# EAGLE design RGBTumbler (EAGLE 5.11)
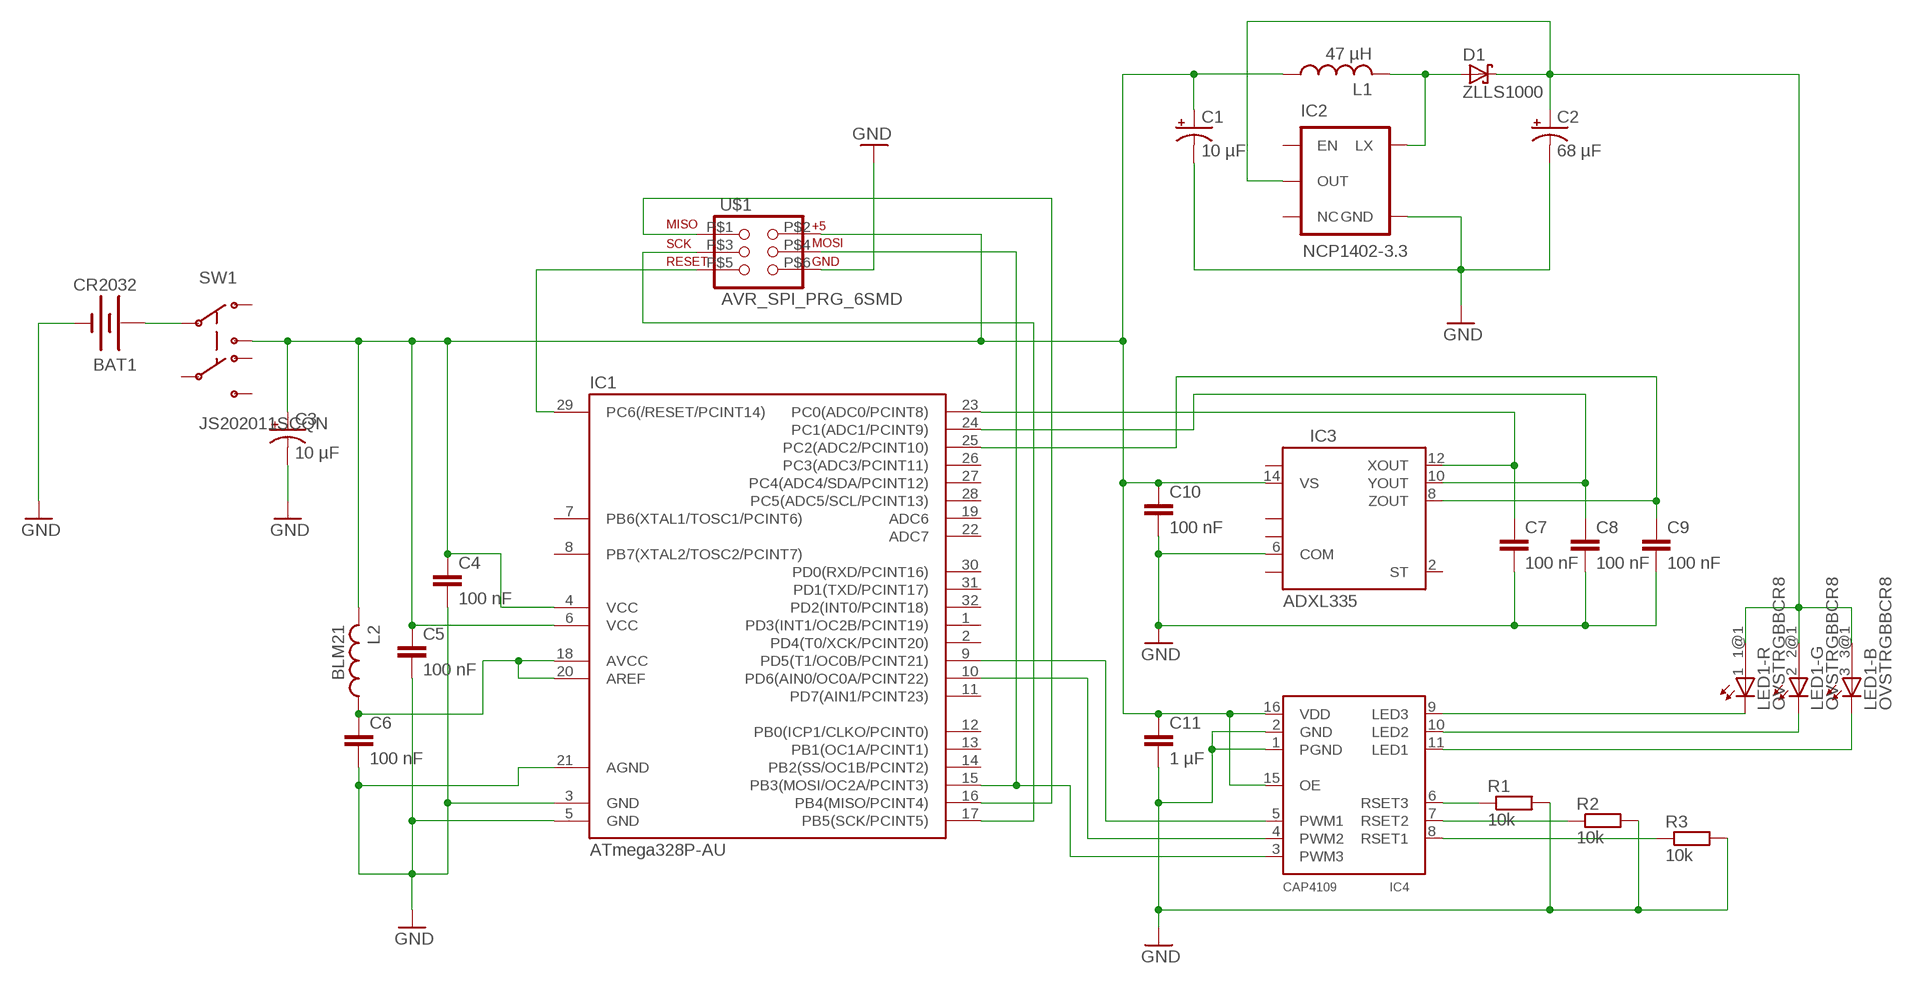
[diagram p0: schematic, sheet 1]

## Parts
BAT1  CR2032  BATTERY20SMD-RIGHT  [BATTCON_20MM]
C1  10 µF  CPOL-USSMCB  [SMC_B]
C2  68 µF  CPOL-USSMCB  [SMC_B]
C3  10 µF  CPOL-USSMCB  [SMC_B]
C4  100 nF  CAP0805  [0805]
C5  100 nF  CAP0805  [0805]
C6  100 nF  CAP0805  [0805]
C7  100 nF  CAP0805  [0805]
C8  100 nF  CAP0805  [0805]
C9  100 nF  CAP0805  [0805]
C10  100 nF  CAP0805  [0805]
C11  1 µF  C-EUC1206  [C1206]
D1  ZLLS1000  BAS40  [SOT23]
IC1  ATmega328P-AU  MEGA48/88/168-AU  [TQFP32-08]
IC2  NCP1402-3.3  V_REG_NCP1400SOT23-5  [SOT23-5]
IC3  ADXL335  ADXL335LONG_PADS  [LFCSP-16-HAND]
IC4  CAP4109  [SO16]
L1  47 µH  PANASONIC_ELL5PS  [ELL5PS_INDUCTOR]
L2  BLM21  BLM21A  [0805]
LED1  OVSTRGBBCR8  [OVSTRGBBCR8]
R1  10k  R-EU_M1206  [M1206]
R2  10k  R-EU_M1206  [M1206]
R3  10k  R-EU_M1206  [M1206]
SW1  JS202011SCQN  SW_DPDT_JS202011SCQN  [JS202011SCQN_DPDT]
U$1  AVR_SPI_PRG_6SMD  [2X3_SMD]

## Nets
GND: BAT1.2(-) C1.- C2.- C3.- C4.2 C5.2 C6.2 C7.2 C8.2 C9.2 C10.2 C11.2 IC1.3(GND) IC1.5(GND) IC1.21(AGND) IC2.4(GND) IC3.6(COM) IC4.1(PGND) IC4.2(GND) R1.2 R2.2 R3.2 U$1.P$6
MISO: IC1.16(PB4(MISO/PCINT4)) U$1.P$1
MOSI: IC1.15(PB3(MOSI/OC2A/PCINT3)) IC4.3(PWM3) U$1.P$4
N$1: IC4.6(RSET3) R1.1
N$2: D1.1(A) IC2.5(LX) L1.P$2
N$3: IC4.7(RSET2) R2.1
N$4: IC4.8(RSET1) R3.1
N$5: IC4.11(LED1) LED1.4(-B:C)
N$6: C6.1 IC1.18(AVCC) IC1.20(AREF) L2.1
N$7: IC4.10(LED2) LED1.5(-G:C)
N$8: IC4.9(LED3) LED1.6(-R:C)
N$10: IC1.9(PD5(T1/OC0B/PCINT21)) IC4.5(PWM1)
N$11: IC1.10(PD6(AIN0/OC0A/PCINT22)) IC4.4(PWM2)
N$13: C7.1 IC1.23(PC0(ADC0/PCINT8)) IC3.12(XOUT)
N$14: C8.1 IC1.24(PC1(ADC1/PCINT9)) IC3.10(YOUT)
N$15: C9.1 IC1.25(PC2(ADC2/PCINT10)) IC3.8(ZOUT)
N$16: BAT1.3(+) SW1.P$2
RESET: IC1.29(PC6(/RESET/PCINT14)) U$1.P$5
SCK: IC1.17(PB5(SCK/PCINT5)) U$1.P$3
VCC: C1.+ C3.+ C4.1 C5.1 C10.1 C11.1 IC1.4(VCC) IC1.6(VCC) IC3.14(VS) IC4.15(OE) IC4.16(VDD) L1.P$1 L2.2 SW1.P$3 U$1.P$2
VLED: C2.+ D1.3(C) IC2.2(OUT) LED1.1@1(-R:A) LED1.2@1(-G:A) LED1.3@1(-B:A)
Unconnected: IC1.1(PD3(INT1/OC2B/PCINT19)) IC1.2(PD4(T0/XCK/PCINT20)) IC1.7(PB6(XTAL1/TOSC1/PCINT6)) IC1.8(PB7(XTAL2/TOSC2/PCINT7)) IC1.11(PD7(AIN1/PCINT23)) IC1.12(PB0(ICP1/CLKO/PCINT0)) IC1.13(PB1(OC1A/PCINT1)) IC1.14(PB2(SS/OC1B/PCINT2)) IC1.19(ADC6) IC1.22(ADC7) IC1.26(PC3(ADC3/PCINT11)) IC1.27(PC4(ADC4/SDA/PCINT12)) IC1.28(PC5(ADC5/SCL/PCINT13)) IC1.30(PD0(RXD/PCINT16)) IC1.31(PD1(TXD/PCINT17)) IC1.32(PD2(INT0/PCINT18)) IC2.1(EN) IC2.3(NC) IC3.2(ST) IC3.3(COM) IC3.5(COM) IC3.7(COM) IC3.15(VS) LED1.1(-R:A) LED1.2(-G:A) LED1.3(-B:A) SW1.P$1 SW1.P$4 SW1.P$5 SW1.P$6

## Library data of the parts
BAT1 = SparkFun:BATTERY: Battery Holders
C1-C3 = rcl:CPOL-US: POLARIZED CAPACITOR, American symbol
C4-C10 = SparkFun:CAP: Capacitor
C11 = rcl:C-EU: CAPACITOR, European symbol
D1 = diode:BAS40: Silicon Schottky Diodes
IC1 = avr-6:MEGA48/88/168
IC2 = SparkFun:V_REG_NCP1400: Switching step-up voltage regulator NCP1400 switiching regulator takes single cell AA and outputs 100mA at 3.3V or 5V with minimal number of external components.
IC3 = jenwilly_custom:ADXL335
IC4 = jenwilly_custom:CAP4109: CAP4109 On Semiconductor CAP4109
L1 = jenwilly_custom:PANASONIC_ELL5PS: Panasonic ELL5PS SMD inductor
L2 = jenwilly_custom:BLM21A: BLM21A SMD Inductor
LED1 = jenwilly_custom:OVSTRGBBCR8: Full Color PLCC6 LED OVSTRGBBCR8 Source: www.optekinc.com .. ovstrgbbcr8.pdf
R1-R3 = rcl:R-EU_: RESISTOR, European symbol
SW1 = jenwilly_custom:SW_DPDT_JS202011SCQN: DPDT SMD Switch C&K JS202011SCQN sub-miniature slide switch Contact rating: 6VDC @ 0.3A - 30VDC @ 0.1A Datasheet Digi-Key no: 401-2002-1-ND
U$1 = jenwilly_custom:AVR_SPI_PRG_6: AVR ISP 6 Pin This is the reduced ISP connector for AVR programming. Common on Arduino. This footprint will take up less PCB space and can be used with a 10-pin to 6-pin adapter such as SKU: BOB-08508

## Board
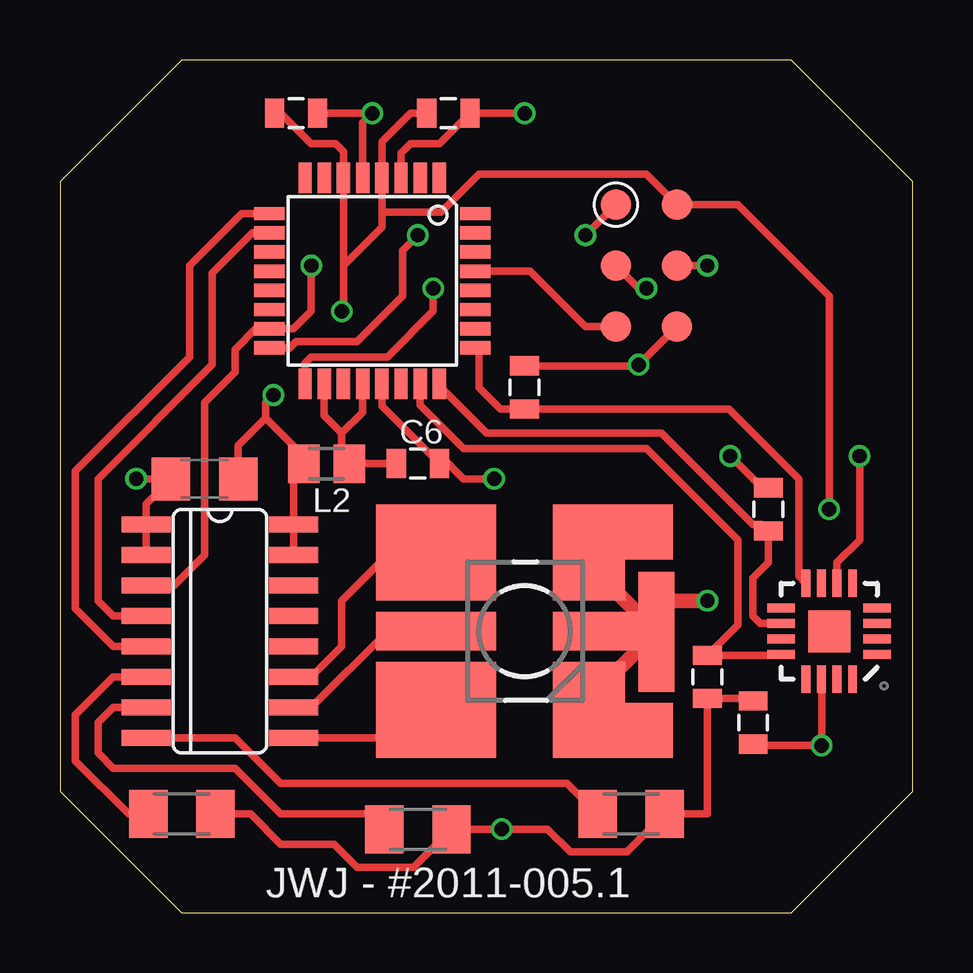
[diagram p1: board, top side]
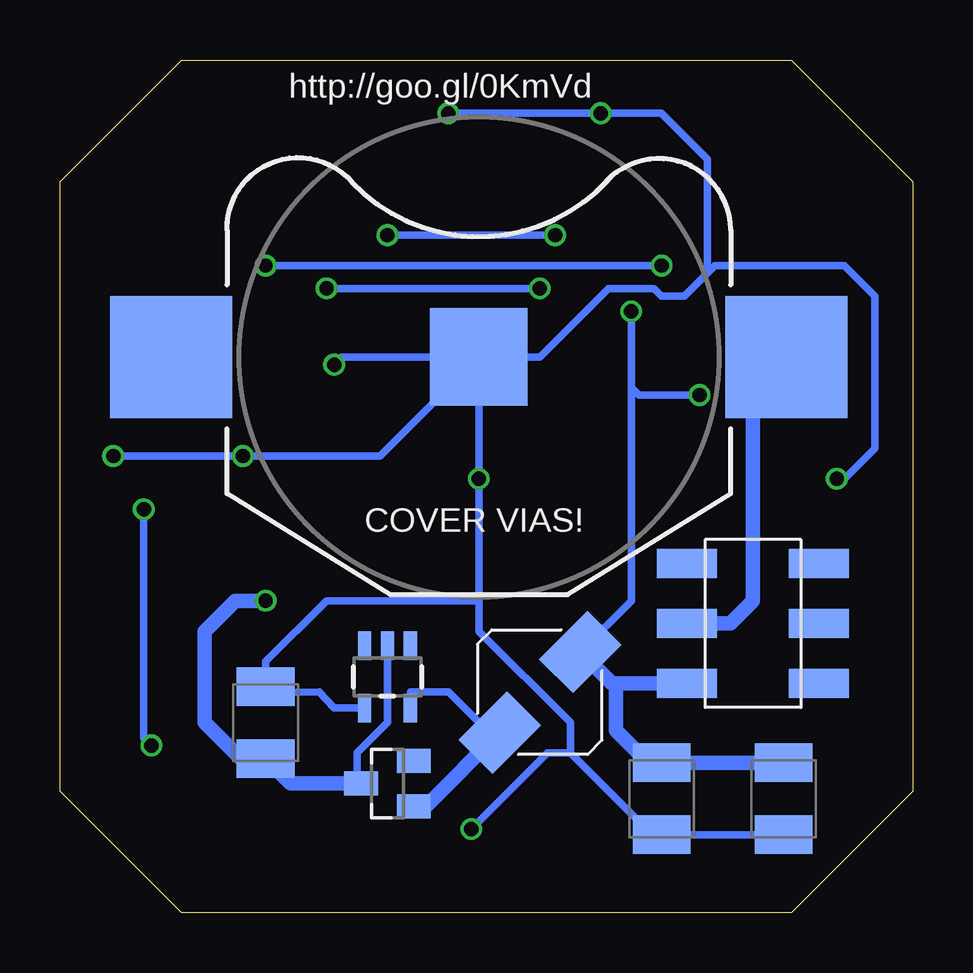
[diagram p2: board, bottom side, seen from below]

Size 35.56 x 35.56 mm. Coordinates in mm from the lower left corner, seen from the top.
Outline: 5.08,0 30.48,0 35.56,5.08 35.56,30.48 30.48,35.56 5.08,35.56 0,30.48 0,5.08 5.08,0
Copper layers (1*16): Top 0.035mm / dielectric 1.5mm / Bottom 0.035mm
Design rules "ITead_rule": minimum track width 6mil, minimum drill 12mil, track to track 6mil, track to pad 6mil, pad to pad 6mil, via to via 6mil, smd to smd 0mil, copper to edge 10mil, drill to drill 10mil, minimum pad ring 10mil, minimum via ring 6mil, stop-mask expansion 2mil, vias tented up to drill 100mil, thermal gap 10mil

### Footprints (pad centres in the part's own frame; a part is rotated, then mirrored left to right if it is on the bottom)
BATTCON_20MM = smd 5.08 x 5.08: 1 -12.827,0; 3 12.827,0 | smd 4.064 x 4.064: 2 0,0
SMC_B = smd 1.6 x 2.4: + -1.5,0; - 1.5,0
0805 = smd 0.8 x 1.2: 1 -0.9,0; 2 0.9,0
C1206 = smd 1.6 x 1.8: 1 -1.4,0; 2 1.4,0
SOT23 = smd 1 x 1.4: 1 -0.95,-1.1; 2 0.95,-1.1; 3 0,1.1
TQFP32-08 = smd 1.27 x 0.559: 1 -4.293,2.8; 2 -4.293,2; 3 -4.293,1.2; 4 -4.293,0.4; 5 -4.293,-0.4; 6 -4.293,-1.2; 7 -4.293,-2; 8 -4.293,-2.8; 17 4.293,-2.8; 18 4.293,-2; 19 4.293,-1.2; 20 4.293,-0.4; 21 4.293,0.4; 22 4.293,1.2; 23 4.293,2; 24 4.293,2.8 | smd 0.559 x 1.27: 9 -2.8,-4.293; 10 -2,-4.293; 11 -1.2,-4.293; 12 -0.4,-4.293; 13 0.4,-4.293; 14 1.2,-4.293; 15 2,-4.293; 16 2.8,-4.293; 25 2.8,4.293; 26 2,4.293; 27 1.2,4.293; 28 0.4,4.293; 29 -0.4,4.293; 30 -1.2,4.293; 31 -2,4.293; 32 -2.8,4.293
SOT23-5 = smd 0.55 x 1.2: 1 -0.95,-1.3; 2 0,-1.3; 3 0.95,-1.3; 4 0.95,1.3; 5 -0.95,1.3
LFCSP-16-HAND = smd 1.75 x 1.75: 0 0,0 | smd 1.15 x 0.37: 1 -2,0.975; 2 -2,0.325; 3 -2,-0.325; 4 -2,-0.975; 9 2,-0.975; 10 2,-0.325; 11 2,0.325; 12 2,0.975 | smd 0.37 x 1.15: 5 -0.975,-2; 6 -0.325,-2; 7 0.325,-2; 8 0.975,-2; 13 0.975,2; 14 0.325,2; 15 -0.325,2; 16 -0.975,2
SO16 = smd 0.66 x 2.032: 1 -4.445,-3.073; 2 -3.175,-3.073; 3 -1.905,-3.073; 4 -0.635,-3.073; 5 0.635,-3.073; 6 1.905,-3.073; 7 3.175,-3.073; 8 4.445,-3.073; 9 4.445,3.073; 10 3.175,3.073; 11 1.905,3.073; 12 0.635,3.073; 13 -0.635,3.073; 14 -1.905,3.073; 15 -3.175,3.073; 16 -4.445,3.073
ELL5PS_INDUCTOR = smd 2.85 x 2 rotated 225: P$1 1.686,1.672; P$2 -1.672,-1.686
0805' = smd 1.3 x 1.6: 1 -0.95,0; 2 0.95,0
OVSTRGBBCR8 = smd 3 x 4: 1 2.692,-3.286; 3 2.692,3.286 | smd 5 x 2.3: 1@1 3.692,-4.136; 3@1 3.692,4.136 | smd 5 x 1.6: 2 3.692,0; 5 -3.692,0 | smd 1.5 x 5: 2@1 5.5,-0.025 | smd 5 x 4: 4 -3.692,3.286; 6 -3.692,-3.286
M1206 = smd 1.6 x 2: 1 -1.4,0; 2 1.4,0
JS202011SCQN_DPDT = smd 1.2 x 2.5: P$1 -2.5,-2.75; P$2 0,-2.75; P$3 2.5,-2.75; P$4 2.5,2.75; P$5 0,2.75; P$6 -2.5,2.75
2X3_SMD = smd 1.27 x 1.27: P$1 0,0; P$2 0,2.54; P$3 2.54,0; P$4 2.54,2.54; P$5 5.08,0; P$6 5.08,2.54

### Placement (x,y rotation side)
BAT1  18.1,23.18 0 bottom
C1  5.4,4.76 270 bottom
C2  26.99,7.94 90 bottom
C3  10.48,4.76 270 bottom
C4  16.19,33.34 0 top
C5  9.84,33.34 0 top
C6  14.92,18.73 0 top
C7  26.99,9.84 270 top
C8  29.53,16.83 90 top
C9  19.37,21.91 90 top
C10  28.89,7.94 90 top
C11  6.03,18.1 180 top
D1  21.91,5.4 90 bottom
IC1  13.02,26.35 270 top
IC2  21.91,9.84 180 bottom
IC3  32.07,11.75 180 top
IC4  6.67,11.75 270 top
L1  15.56,9.21 0 bottom
L2  BLM21  [0805']  11.11,18.73 180 top
LED1  19.37,11.75 0 top
R1  5.08,4.13 0 top
R2  14.92,3.49 0 top
R3  23.81,4.13 0 top
SW1  6.67,12.06 270 bottom
U$1  23.18,29.53 270 top

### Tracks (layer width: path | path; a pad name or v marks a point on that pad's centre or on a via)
GND  (via drill 0.6)
  Top 0.305: IC4.2 IC4.1 3.59,17.06 C11.2 v3.17,18.1 | 13.42,21.51 IC1.21 13.42,21.14 C6.2 15.82,19.1 16.83,18.1 v18.1,18.1 | C5.2 v13.02,33.34 12.62,32.94 IC1.5 | C8.2 29.26,17.73 v27.94,19.05 | IC1.3 14.22,31.68 14.61,32.07 15.82,32.07 C4.2 v19.37,33.34 | U$1.P$6 v24.13,22.86 24.08,22.81 C9.2 | R1.2 7.94,4.13 9.21,2.86 11.43,2.86 12.38,1.91 14.73,1.91 R2.2 v18.41,3.49 20.32,3.49 21.27,2.54 23.62,2.54 R3.2 26.99,4.13 C7.2 28.89,8.94 C10.2 | IC3.6 32.39,14.61 33.34,15.56 v33.34,19.05
  Bottom 0.305: C1.- C3.- 11.52,3.9 14.29,6.67 | 14.29,6.67 14.29,7.94 18.1,11.75 18.1,13.02 | IC2.4 24.13,8.54 24.77,9.21 26.73,9.18 C2.- 26.99,10.48 24.45,13.02 18.1,13.02 | BAT1.2 15.56,23.18 12.7,26.04 10.79,26.04 10.48,25.72 9.53,25.72 8.57,26.67 | 8.57,26.67 8.57,31.43 10.48,33.34 v13.02,33.34 v19.37,33.34 | BAT1.2 22.23,19.05 v27.94,19.05 v33.34,19.05 | v3.17,18.1 2.86,18.1 1.59,19.37 1.59,25.72 2.86,26.99 8.26,26.99 8.57,26.67 | 18.1,13.02 v18.1,18.1 BAT1.2 | BAT1.2 23.81,23.18 v24.13,22.86 | 14.29,6.67 15.24,6.67 v18.41,3.49
MISO  (via drill 0.6)
  Top 0.305: IC1.16 9.58,23.55 9.84,23.81 12.38,23.81 14.29,25.72 14.29,27.62 v14.92,28.26 | v21.91,28.26 U$1.P$1
  Bottom 0.305: v14.92,28.26 v21.91,28.26
MOSI  (via drill 0.6)
  Top 0.305: 3.49,13.65 IC4.3 4.76,13.65 6.03,14.92 6.03,21.27 7.3,22.54 7.3,23.5 8.16,24.35 IC1.15 9.75,24.35 10.48,25.08 v10.48,26.99 | v26.99,26.99 U$1.P$4
  Bottom 0.305: v10.48,26.99 v26.99,26.99
N$1
  Top 0.305: R1.1 2.86,4.13 0.64,6.35 0.64,8.26 2.22,9.84 IC4.6
N$2
  Bottom 0.305: L1.P$2 17.68,7.52 19.37,9.21 20.95,9.21 IC2.5
  Bottom 0.61: D1.1 20.3,4.45 L1.P$2
N$3
  Top 0.305: IC4.7 2.22,8.57 1.59,7.94 1.59,6.67 2.22,6.03 7.3,6.03 9.21,4.13 12.89,4.13 R2.1
N$4
  Top 0.305: R3.1 21.14,5.4 9.21,5.4 7.3,7.3 IC4.8
N$5
  Top 0.305: LED1.4 13.76,15.03 11.75,13.02 11.75,11.11 10.48,9.84 IC4.11
N$6
  Top 0.305: L2.1 C6.1 | L2.1 12.62,18.81 | IC1.18 11.02,20.73 11.75,20 | 11.75,20 11.75,19.05 L2.1 | IC1.20 12.62,20.87 11.75,20
N$7
  Top 0.305: LED1.5 13.65,11.75 10.48,8.57 IC4.10
N$8
  Top 0.305: IC4.9 14.52,7.3 LED1.6
N$10
  Top 0.305: IC4.5 2.22,11.11 0.64,12.7 0.64,18.41 5.4,23.18 5.4,26.99 7.56,29.15 IC1.9
N$11
  Top 0.305: IC4.4 2.22,12.38 1.59,13.02 1.59,18.1 6.35,22.86 6.35,26.67 8.03,28.35 IC1.10
N$13
  Top 0.305: IC1.23 15.02,21.18 16.83,19.37 24.45,19.37 28.26,15.56 28.26,12.01 C7.1 30.04,10.74 IC3.12
N$14
  Top 0.305: C8.1 29.16,15.93 | IC1.24 15.82,21.96 17.78,20 25.08,20 28.89,16.19 29.26,16.19 C8.1 | IC3.10 29.2,12.07 28.89,12.38 28.89,13.97 29.53,14.61 C8.1
N$15
  Top 0.305: IC1.25 17.46,23.4 17.46,21.91 18.36,21.01 C9.1 27.89,21.01 30.8,18.1 30.8,14.04 IC3.8
N$16
  Bottom 0.61: BAT1.3 6.67,21.78 6.67,13.02 7.62,12.06 SW1.P$2
RESET
  Top 0.305: IC1.29 19.6,26.75 21.91,24.45 U$1.P$5
SCK  (via drill 0.6)
  Top 0.305: IC1.17 10.22,22.92 10.48,23.18 13.65,23.18 15.56,25.08 v15.56,26.04 | 23.5,26.99 U$1.P$3 24.13,26.04 v24.45,26.04
  Bottom 0.305: v15.56,26.04 v24.45,26.04
VCC  (via drill 0.6)
  Top 0.305: 8.57,20.64 10.16,19.05 L2.2 9.74,18.31 IC4.16 IC4.15 | C11.1 7.43,19.5 8.57,20.64 | 11.82,26.99 11.82,25.15 v11.75,25.08 | 11.82,26.99 IC1.6 11.82,31.73 11.48,32.07 10.48,32.07 9.21,33.34 C5.1 | 13.42,29.21 13.42,28.59 11.82,26.99 | 13.42,29.21 IC1.4 13.42,32.15 14.61,33.34 C4.1 | 8.57,20.64 8.57,21.27 v8.89,21.59 | 13.42,29.21 15.88,29.21 17.46,30.8 24.45,30.8 U$1.P$2 28.26,29.53 32.07,25.72 v32.07,16.83 | IC3.14 v31.75,6.99 28.95,6.99 C10.1
  Bottom 0.305: L1.P$1 13.87,10.89 11.75,13.02 11.75,21.91 | 11.75,21.91 v11.75,25.08 | v8.89,21.59 11.43,21.59 11.75,21.91 | v32.07,16.83 32.07,7.3 v31.75,6.99
  Bottom 0.61: C1.+ C3.+ 11.03,6.26 12.38,7.62 12.38,9.39 12.56,9.56 | 12.56,9.56 SW1.P$3 | 12.56,9.56 L1.P$1
VLED  (via drill 0.6)
  Top 0.61: LED1.2@1 24.87,12.6 24.45,13.02 v26.99,13.02 | LED1.1@1 23.06,9.91 LED1.2@1 | LED1.3@1 23.06,13.53 LED1.2@1
  Bottom 0.305: D1.3 23.18,5.57 23.18,6.67 21.91,7.94 IC2.2
  Bottom 0.61: D1.3 25.95,5.4 C2.+ 28.03,6.44 29.53,7.94 29.53,11.75 28.26,13.02 v26.99,13.02

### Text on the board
tPlace: JWJ - #2011-005.1
bPlace: http://goo.gl/0KmVd | COVER VIAS!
